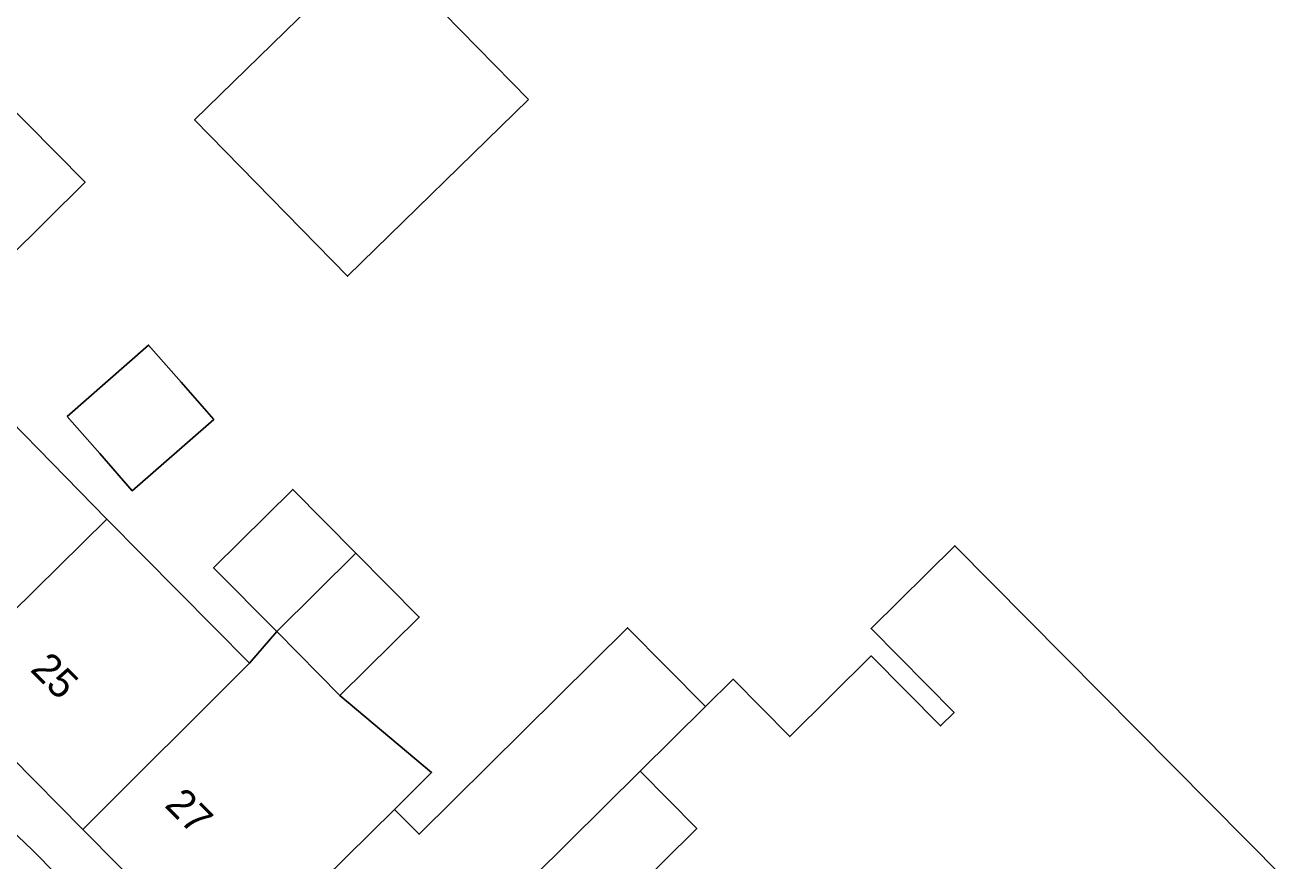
# Model space of a CAD drawing. Extents: x 160107 to 160928, y 382056 to 382918.
# Drawn here: x 160677.52 to 160720.42, y 382635.99 to 382664.5 of the extents above; entities that cross this region are included whole.
import ezdxf

# ---------------------------------------------------------------- set-up
doc = ezdxf.new("R2010")
doc.units = 0
for name, color, linetype in [('IMGEO_Pand', 7, 'Continuous'), ('IMGEO_Pand_nummerreeks', 7, 'Continuous'), ('IMGEO_Rijbaan_lokaal_open', 7, 'Continuous'), ('IMGEO_Voetpad_open', 7, 'Continuous')]:
    doc.layers.add(name, color=color, linetype=linetype)

msp = doc.modelspace()

# ---------------------------------------------------------------- linework, layer by layer
at = {"layer": 'IMGEO_Pand'}
for points in [[(160694.686, 382661.966), (160688.516, 382655.934), (160683.3, 382661.269), (160689.47, 382667.302), (160694.686, 382661.966)], [(160672.007, 382661.561), (160674.579, 382664.179), (160679.567, 382659.14), (160674.237, 382653.864), (160668.534, 382648.218)], [(160682.845, 382652.318), (160683.955, 382651.052), (160681.178, 382648.616), (160680.068, 382649.882), (160678.957, 382651.148), (160681.734, 382653.584), (160682.845, 382652.318)], [(160669.618, 382647.108), (160675.152, 382652.928), (160680.312, 382647.65)], [(160686.104, 382643.812), (160683.947, 382645.99), (160686.648, 382648.664), (160688.805, 382646.486)], [(160674.589, 382642.015), (160680.312, 382647.65)], [(160680.312, 382647.65), (160685.179, 382642.734)], [(160700.729, 382641.256), (160701.666, 382642.184), (160703.6, 382640.231), (160706.377, 382642.98), (160708.74, 382640.592), (160709.205, 382641.053), (160706.373, 382643.913), (160709.229, 382646.741), (160720.417, 382635.44), (160704.173, 382619.357), (160700.781, 382615.999)], [(160686.104, 382643.812), (160688.805, 382646.486)], [(160688.805, 382646.486), (160690.961, 382644.308), (160688.26, 382641.634)], [(160685.179, 382642.734), (160686.104, 382643.812)], [(160688.26, 382641.634), (160686.104, 382643.812)], [(160690.117, 382637.747), (160690.956, 382636.899), (160698.07, 382643.942), (160700.729, 382641.256)], [(160685.179, 382642.734), (160679.49, 382637.064)], [(160679.49, 382637.064), (160674.589, 382642.015)], [(160688.26, 382641.634), (160691.386, 382639.003), (160690.117, 382637.747)], [(160698.496, 382639.045), (160700.729, 382641.256)], [(160698.496, 382639.045), (160693.616, 382634.213), (160692.728, 382633.334)], [(160692.728, 382633.334), (160694.662, 382631.381), (160700.43, 382637.092), (160698.496, 382639.045)], [(160684.405, 382632.1), (160690.117, 382637.747)], [(160684.405, 382632.1), (160679.49, 382637.064)]]:
    msp.add_lwpolyline(points, dxfattribs=at)
at = {"layer": 'IMGEO_Rijbaan_lokaal_open'}
msp.add_arc((160645.108, 382603.375), 44.625, 43.4149, 59.1365, dxfattribs=at)
at = {"layer": 'IMGEO_Voetpad_open'}
msp.add_lwpolyline([(160677.77, 382636.349), (160694.982, 382618.904), (160693.909, 382617.859), (160694.552, 382617.243), (160695.607, 382618.271), (160714.45, 382599.171)], dxfattribs=at)
msp.add_arc((160644.698, 382603.008), 46.962, 45.2318, 58.7473, dxfattribs=at)

# ---------------------------------------------------------------- texts
at = {"layer": 'IMGEO_Pand_nummerreeks'}
for s, rotation, p in [('25', 314.7138, (160677.665, 382642.49)), ('27', 314.7134, (160682.245, 382637.862))]:
    msp.add_text(s, height=1, rotation=rotation, dxfattribs=at).set_placement(p)

doc.saveas('drawing.dxf')
